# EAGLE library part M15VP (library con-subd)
SUB-D
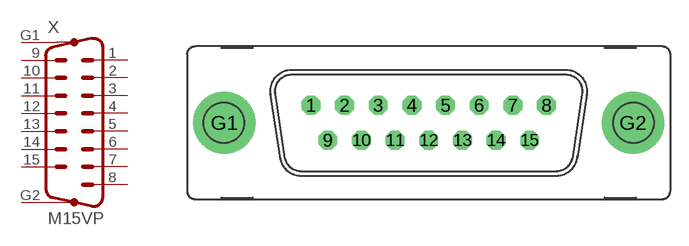
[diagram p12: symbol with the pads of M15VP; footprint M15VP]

Designator prefix X

## M15VP (OC_FARNELL: unknown; OC_NEWARK: unknown)  [M15VP]
1  1  pas
2  2  pas
3  3  pas
4  4  pas
5  5  pas
6  6  pas
7  7  pas
8  8  pas
9  9  pas
10  10  pas
11  11  pas
12  12  pas
13  13  pas
14  14  pas
15  15  pas
G1  G1  pas
G2  G2  pas

## Footprint M15VP (pad centres in mm)
SUB-D
drill 1.016 octagon: 1 -9.601,1.422; 2 -6.858,1.422; 3 -4.115,1.422; 4 -1.372,1.422; 5 1.372,1.422; 6 4.115,1.422; 7 6.858,1.422; 8 9.601,1.422; 9 -8.23,-1.422; 10 -5.486,-1.422; 11 -2.743,-1.422; 12 0,-1.422; 13 2.743,-1.422; 14 5.486,-1.422; 15 8.23,-1.422
drill 3.302 pad 5.08 round: G1 -16.662,0; G2 16.662,0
